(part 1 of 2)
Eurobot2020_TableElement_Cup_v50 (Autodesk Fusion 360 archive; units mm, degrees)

design "TableElement2020" references "Balise Rouge", "Table2020", "Balise Verte"
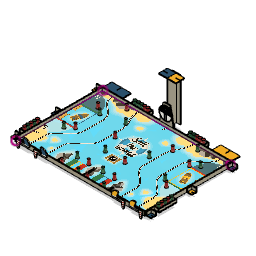
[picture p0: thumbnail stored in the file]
component_insert "Component Insert1"
component_insert "Component Insert21"
component_insert "Component Insert22"
component_insert "Component Insert23"
component_insert "Component Insert24"
component_insert "Component Insert25"
component_insert "Component Insert26"
component_insert "Component Insert27"
component_insert "Component Insert28"
component_insert "Component Insert29"
component_insert "Component Insert30"
component_insert "Component Insert31"
component_insert "Component Insert32"
component_insert "Component Insert33"
component_insert "Component Insert34"
component_insert "Component Insert35"
component_insert "Component Insert36"
component_insert "Component Insert37"
component_insert "Component Insert38"
component_insert "Component Insert39"
component_insert "Component Insert40"
component_insert "Component Insert41"
component_insert "Component Insert42"
component_insert "Component Insert43"
component_insert "Component Insert44"
component_insert "Component Insert45"
component_insert "Component Insert46"
component_insert "Component Insert47"
component_insert "Component Insert48"
component_insert "Component Insert49"
component_insert "Component Insert50"
component_insert "Component Insert51"
component_insert "Component Insert52"
component_insert "Component Insert53"
component_insert "Component Insert54"
component_insert "Component Insert55"
component_insert "Component Insert56"
position "Position1"
joint "Assemble1" OffsetX 0 OffsetY 0 OffsetZ 0 AngleZ 0 OffsetX 0 OffsetY 0 OffsetZ 0 AngleZ 0 alignAngle 0 alignOffsetX 300 alignOffsetY -400 alignOffsetZ 0 OffsetX 0 OffsetY 0 OffsetZ 0 AngleZ 0 OffsetX 0 OffsetY 0 OffsetZ 0 AngleZ 0 OffsetX 0 OffsetY 0 OffsetZ 0 AngleZ 0 OffsetX 0 OffsetY 0 OffsetZ 0 AngleZ 0 OffsetX 0 OffsetY 0 OffsetZ 0 AngleZ 0 OffsetX 0 OffsetY 0 OffsetZ 0 AngleZ 0 OffsetX 0 OffsetY 0 OffsetZ 0 AngleZ 0 OffsetX 0 OffsetY 0 OffsetZ 0 AngleZ 0 OffsetX 0 OffsetY 0 OffsetZ 0 AngleZ 0 OffsetX 0 OffsetY 0 OffsetZ 0 AngleZ 0
joint "Assemble2" OffsetX 0 OffsetY 0 OffsetZ 0 AngleZ 0 OffsetX 0 OffsetY 0 OffsetZ 0 AngleZ 0 alignAngle 0 alignOffsetX 450 alignOffsetY -509 alignOffsetZ 0 OffsetX 0 OffsetY 0 OffsetZ 0 AngleZ 0 OffsetX 0 OffsetY 0 OffsetZ 0 AngleZ 0 OffsetX 0 OffsetY 0 OffsetZ 0 AngleZ 0 OffsetX 0 OffsetY 0 OffsetZ 0 AngleZ 0
joint "Assemble3" OffsetX 0 OffsetY 0 OffsetZ 0 AngleZ 0 OffsetX 0 OffsetY 0 OffsetZ 0 AngleZ 0 alignAngle 0 alignOffsetX 450 alignOffsetY -1080 alignOffsetZ 0 OffsetX 0 OffsetY 0 OffsetZ 0 AngleZ 0 OffsetX 0 OffsetY 0 OffsetZ 0 AngleZ 0
joint "Assemble4" OffsetX 0 OffsetY 0 OffsetZ 0 AngleZ 0 OffsetX 0 OffsetY 0 OffsetZ 0 AngleZ 0 alignAngle 0 alignOffsetX 300 alignOffsetY -1200 alignOffsetZ 0 OffsetX 0 OffsetY 0 OffsetZ 0 AngleZ 0 OffsetX 0 OffsetY 0 OffsetZ 0 AngleZ 0
joint "Assemble5" OffsetX 0 OffsetY 0 OffsetZ 0 AngleZ 0 OffsetX 0 OffsetY 0 OffsetZ 0 AngleZ 0 alignAngle 0 alignOffsetX 670 alignOffsetY -100 alignOffsetZ 0 OffsetX 0 OffsetY 0 OffsetZ 0 AngleZ 0 OffsetX 0 OffsetY 0 OffsetZ 0 AngleZ 0 OffsetX 0 OffsetY 0 OffsetZ 0 AngleZ 0 OffsetX 0 OffsetY 0 OffsetZ 0 AngleZ 0 OffsetX 0 OffsetY 0 OffsetZ 0 AngleZ 0 OffsetX 0 OffsetY 0 OffsetZ 0 AngleZ 0
joint "Assemble6" OffsetX 0 OffsetY 0 OffsetZ 0 AngleZ 0 OffsetX 0 OffsetY 0 OffsetZ 0 AngleZ 0 alignAngle 0 alignOffsetX 950 alignOffsetY -400 alignOffsetZ 0 OffsetX 0 OffsetY 0 OffsetZ 0 AngleZ 0 OffsetX 0 OffsetY 0 OffsetZ 0 AngleZ 0 OffsetX 0 OffsetY 0 OffsetZ 0 AngleZ 0 OffsetX 0 OffsetY 0 OffsetZ 0 AngleZ 0
joint "Assemble7" OffsetX 0 OffsetY 0 OffsetZ 0 AngleZ 0 OffsetX 0 OffsetY 0 OffsetZ 0 AngleZ 0 alignAngle 0 alignOffsetX 1100 alignOffsetY -800 alignOffsetZ 0 OffsetX 0 OffsetY 0 OffsetZ 0 AngleZ 0 OffsetX 0 OffsetY 0 OffsetZ 0 AngleZ 0 OffsetX 0 OffsetY 0 OffsetZ 0 AngleZ 0 OffsetX 0 OffsetY 0 OffsetZ 0 AngleZ 0
joint "Assemble8" OffsetX 0 OffsetY 0 OffsetZ 0 AngleZ 0 OffsetX 0 OffsetY 0 OffsetZ 0 AngleZ 0 alignAngle 0 alignOffsetX 1270 alignOffsetY -1200 alignOffsetZ 0 OffsetX 0 OffsetY 0 OffsetZ 0 AngleZ 0 OffsetX 0 OffsetY 0 OffsetZ 0 AngleZ 0 OffsetX 0 OffsetY 0 OffsetZ 0 AngleZ 0 OffsetX 0 OffsetY 0 OffsetZ 0 AngleZ 0
joint "Assemble9" OffsetX 0 OffsetY 0 OffsetZ 0 AngleZ 0 OffsetX 0 OffsetY 0 OffsetZ 0 AngleZ 0 alignAngle 0 alignOffsetX 1730 alignOffsetY -1200 alignOffsetZ 0 OffsetX 0 OffsetY 0 OffsetZ 0 AngleZ 0 OffsetX 0 OffsetY 0 OffsetZ 0 AngleZ 0
joint "Assemble10" OffsetX 0 OffsetY 0 OffsetZ 0 AngleZ 0 OffsetX 0 OffsetY 0 OffsetZ 0 AngleZ 0 alignAngle 0 alignOffsetX 1900 alignOffsetY -800 alignOffsetZ 0 OffsetX 0 OffsetY 0 OffsetZ 0 AngleZ 0 OffsetX 0 OffsetY 0 OffsetZ 0 AngleZ 0
joint "Assemble11" OffsetX 0 OffsetY 0 OffsetZ 0 AngleZ 0 OffsetX 0 OffsetY 0 OffsetZ 0 AngleZ 0 alignAngle 0 alignOffsetX 2050 alignOffsetY -400 alignOffsetZ 0 OffsetX 0 OffsetY 0 OffsetZ 0 AngleZ 0 OffsetX 0 OffsetY 0 OffsetZ 0 AngleZ 0 OffsetX 0 OffsetY 0 OffsetZ 0 AngleZ 0 OffsetX 0 OffsetY 0 OffsetZ 0 AngleZ 0
joint "Assemble12" OffsetX 0 OffsetY 0 OffsetZ 0 AngleZ 0 OffsetX 0 OffsetY 0 OffsetZ 0 AngleZ 0 alignAngle 0 alignOffsetX 2330 alignOffsetY -100 alignOffsetZ 0 OffsetX 0 OffsetY 0 OffsetZ 0 AngleZ 0 OffsetX 0 OffsetY 0 OffsetZ 0 AngleZ 0
joint "Assemble13" OffsetX 0 OffsetY 0 OffsetZ 0 AngleZ 0 OffsetX 0 OffsetY 0 OffsetZ 0 AngleZ 0 alignAngle 0 alignOffsetX 2700 alignOffsetY -400 alignOffsetZ 0
joint "Assemble14" OffsetX 0 OffsetY 0 OffsetZ 0 AngleZ 0 OffsetX 0 OffsetY 0 OffsetZ 0 AngleZ 0 alignAngle 0 alignOffsetX 2550 alignOffsetY -510 alignOffsetZ 0 OffsetX 0 OffsetY 0 OffsetZ 0 AngleZ 0 OffsetX 0 OffsetY 0 OffsetZ 0 AngleZ 0 OffsetX 0 OffsetY 0 OffsetZ 0 AngleZ 0 OffsetX 0 OffsetY 0 OffsetZ 0 AngleZ 0
joint "Assemble15" OffsetX 0 OffsetY 0 OffsetZ 0 AngleZ 0 OffsetX 0 OffsetY 0 OffsetZ 0 AngleZ 0 alignAngle 0 alignOffsetX 2550 alignOffsetY -1080 alignOffsetZ 0 OffsetX 0 OffsetY 0 OffsetZ 0 AngleZ 0 OffsetX 0 OffsetY 0 OffsetZ 0 AngleZ 0 OffsetX 0 OffsetY 0 OffsetZ 0 AngleZ 0 OffsetX 0 OffsetY 0 OffsetZ 0 AngleZ 0
joint "Assemble16" OffsetX 0 OffsetY 0 OffsetZ 0 AngleZ 0 OffsetX 0 OffsetY 0 OffsetZ 0 AngleZ 0 alignAngle 0 alignOffsetX 2700 alignOffsetY -1200 alignOffsetZ 0
joint "Assemble17" OffsetX 0 OffsetY 0 OffsetZ 0 AngleZ 0 OffsetX 0 OffsetY 0 OffsetZ 0 AngleZ 0 alignAngle 0 alignOffsetX 1335 alignOffsetY -1650 alignOffsetZ 0 OffsetX 0 OffsetY 0 OffsetZ 0 AngleZ 0 OffsetX 0 OffsetY 0 OffsetZ 0 AngleZ 0 OffsetX 0 OffsetY 0 OffsetZ 0 AngleZ 0 OffsetX 0 OffsetY 0 OffsetZ 0 AngleZ 0
joint "Assemble18" OffsetX 0 OffsetY 0 OffsetZ 0 AngleZ 0 OffsetX 0 OffsetY 0 OffsetZ 0 AngleZ 0 alignAngle 0 alignOffsetX 1065 alignOffsetY -1650 alignOffsetZ 0 OffsetX 0 OffsetY 0 OffsetZ 0 AngleZ 0 OffsetX 0 OffsetY 0 OffsetZ 0 AngleZ 0 OffsetX 0 OffsetY 0 OffsetZ 0 AngleZ 0 OffsetX 0 OffsetY 0 OffsetZ 0 AngleZ 0
joint "Assemble19" OffsetX 0 OffsetY 0 OffsetZ 0 AngleZ 0 OffsetX 0 OffsetY 0 OffsetZ 0 AngleZ 0 alignAngle 0 alignOffsetX 1005 alignOffsetY -1955 alignOffsetZ 0 OffsetX 0 OffsetY 0 OffsetZ 0 AngleZ 0 OffsetX 0 OffsetY 0 OffsetZ 0 AngleZ 0 OffsetX 0 OffsetY 0 OffsetZ 0 AngleZ 0 OffsetX 0 OffsetY 0 OffsetZ 0 AngleZ 0 OffsetX 0 OffsetY 0 OffsetZ 0 AngleZ 0 OffsetX 0 OffsetY 0 OffsetZ 0 AngleZ 0 OffsetX 0 OffsetY 0 OffsetZ 0 AngleZ 0 OffsetX 0 OffsetY 0 OffsetZ 0 AngleZ 0
joint "Assemble20" OffsetX 0 OffsetY 0 OffsetZ 0 AngleZ 0 OffsetX 0 OffsetY 0 OffsetZ 0 AngleZ 0 alignAngle 0 alignOffsetX 1395 alignOffsetY -1955 alignOffsetZ 0 OffsetX 0 OffsetY 0 OffsetZ 0 AngleZ 0 OffsetX 0 OffsetY 0 OffsetZ 0 AngleZ 0 OffsetX 0 OffsetY 0 OffsetZ 0 AngleZ 0 OffsetX 0 OffsetY 0 OffsetZ 0 AngleZ 0
joint "Assemble21" OffsetX 0 OffsetY 0 OffsetZ 0 AngleZ 0 OffsetX 0 OffsetY 0 OffsetZ 0 AngleZ 0 alignAngle 0 alignOffsetX 1935 alignOffsetY -1650 alignOffsetZ 0 OffsetX 0 OffsetY 0 OffsetZ 0 AngleZ 0 OffsetX 0 OffsetY 0 OffsetZ 0 AngleZ 0 OffsetX 0 OffsetY 0 OffsetZ 0 AngleZ 0 OffsetX 0 OffsetY 0 OffsetZ 0 AngleZ 0
joint "Assemble22" OffsetX 0 OffsetY 0 OffsetZ 0 AngleZ 0 OffsetX 0 OffsetY 0 OffsetZ 0 AngleZ 0 alignAngle 0 alignOffsetX 1665 alignOffsetY -1650 alignOffsetZ 0 OffsetX 0 OffsetY 0 OffsetZ 0 AngleZ 0 OffsetX 0 OffsetY 0 OffsetZ 0 AngleZ 0 OffsetX 0 OffsetY 0 OffsetZ 0 AngleZ 0 OffsetX 0 OffsetY 0 OffsetZ 0 AngleZ 0
joint "Assemble23" OffsetX 0 OffsetY 0 OffsetZ 0 AngleZ 0 OffsetX 0 OffsetY 0 OffsetZ 0 AngleZ 0 alignAngle 0 alignOffsetX 1605 alignOffsetY -1955 alignOffsetZ 0 OffsetX 0 OffsetY 0 OffsetZ 0 AngleZ 0 OffsetX 0 OffsetY 0 OffsetZ 0 AngleZ 0 OffsetX 0 OffsetY 0 OffsetZ 0 AngleZ 0 OffsetX 0 OffsetY 0 OffsetZ 0 AngleZ 0
joint "Assemble24" OffsetX 0 OffsetY 0 OffsetZ 0 AngleZ 0 OffsetX 0 OffsetY 0 OffsetZ 0 AngleZ 0 alignAngle 0 alignOffsetX 1995 alignOffsetY -1955 alignOffsetZ 0 OffsetX 0 OffsetY 0 OffsetZ 0 AngleZ 0 OffsetX 0 OffsetY 0 OffsetZ 0 AngleZ 0 OffsetX 0 OffsetY 0 OffsetZ 0 AngleZ 0 OffsetX 0 OffsetY 0 OffsetZ 0 AngleZ 0
joint "Assemble25" OffsetX 0 OffsetY 0 OffsetZ 0 AngleZ 0 OffsetX 0 OffsetY 0 OffsetZ 0 AngleZ 0 alignAngle 0 alignOffsetX -67 (= "-22 mm - 45 mm") alignOffsetY -1450 alignOffsetZ 130 OffsetX 0 OffsetY 0 OffsetZ 0 AngleZ 0 OffsetX 0 OffsetY 0 OffsetZ 0 AngleZ 0 OffsetX 0 OffsetY 0 OffsetZ 0 AngleZ 0 OffsetX 0 OffsetY 0 OffsetZ 0 AngleZ 0 OffsetX 0 OffsetY 0 OffsetZ 0 AngleZ 0 OffsetX 0 OffsetY 0 OffsetZ 0 AngleZ 0 OffsetX 0 OffsetY 0 OffsetZ 0 AngleZ 0 OffsetX 0 OffsetY 0 OffsetZ 0 AngleZ 0 OffsetX 0 OffsetY 0 OffsetZ 0 AngleZ 0 OffsetX 0 OffsetY 0 OffsetZ 0 AngleZ 0 OffsetX 0 OffsetY 0 OffsetZ 0 AngleZ 0 OffsetX 0 OffsetY 0 OffsetZ 0 AngleZ 0 OffsetX 0 OffsetY 0 OffsetZ 0 AngleZ 0 OffsetX 0 OffsetY 0 OffsetZ 0 AngleZ 0 OffsetX 0 OffsetY 0 OffsetZ 0 AngleZ 0 OffsetX 0 OffsetY 0 OffsetZ 0 AngleZ 0
joint "Assemble26" OffsetX 0 OffsetY 0 OffsetZ 0 AngleZ 0 OffsetX 0 OffsetY 0 OffsetZ 0 AngleZ 0 alignAngle 0 alignOffsetX -67 (= "-22 mm - 45 mm") alignOffsetY -1525 alignOffsetZ 130 OffsetX 0 OffsetY 0 OffsetZ 0 AngleZ 0 OffsetX 0 OffsetY 0 OffsetZ 0 AngleZ 0 OffsetX 0 OffsetY 0 OffsetZ 0 AngleZ 0 OffsetX 0 OffsetY 0 OffsetZ 0 AngleZ 0 OffsetX 0 OffsetY 0 OffsetZ 0 AngleZ 0 OffsetX 0 OffsetY 0 OffsetZ 0 AngleZ 0 OffsetX 0 OffsetY 0 OffsetZ 0 AngleZ 0 OffsetX 0 OffsetY 0 OffsetZ 0 AngleZ 0 OffsetX 0 OffsetY 0 OffsetZ 0 AngleZ 0 OffsetX 0 OffsetY 0 OffsetZ 0 AngleZ 0 OffsetX 0 OffsetY 0 OffsetZ 0 AngleZ 0 OffsetX 0 OffsetY 0 OffsetZ 0 AngleZ 0
joint "Assemble27" OffsetX 0 OffsetY 0 OffsetZ 0 AngleZ 0 OffsetX 0 OffsetY 0 OffsetZ 0 AngleZ 0 alignAngle 0 alignOffsetX -67 (= "-22 mm - 45 mm") alignOffsetY -1600 alignOffsetZ 130 OffsetX 0 OffsetY 0 OffsetZ 0 AngleZ 0 OffsetX 0 OffsetY 0 OffsetZ 0 AngleZ 0 OffsetX 0 OffsetY 0 OffsetZ 0 AngleZ 0 OffsetX 0 OffsetY 0 OffsetZ 0 AngleZ 0 OffsetX 0 OffsetY 0 OffsetZ 0 AngleZ 0 OffsetX 0 OffsetY 0 OffsetZ 0 AngleZ 0 OffsetX 0 OffsetY 0 OffsetZ 0 AngleZ 0 OffsetX 0 OffsetY 0 OffsetZ 0 AngleZ 0 OffsetX 0 OffsetY 0 OffsetZ 0 AngleZ 0 OffsetX 0 OffsetY 0 OffsetZ 0 AngleZ 0 OffsetX 0 OffsetY 0 OffsetZ 0 AngleZ 0 OffsetX 0 OffsetY 0 OffsetZ 0 AngleZ 0 OffsetX 0 OffsetY 0 OffsetZ 0 AngleZ 0 OffsetX 0 OffsetY 0 OffsetZ 0 AngleZ 0
component_insert "Component Insert66"
joint "Assemble40" OffsetX 0 OffsetY 0 OffsetZ 0 AngleZ 0 OffsetX 0 OffsetY 0 OffsetZ 0 AngleZ 0 alignAngle 0 alignOffsetX -67 alignOffsetY -1675 alignOffsetZ 130 OffsetX 0 OffsetY 0 OffsetZ 0 AngleZ 0 OffsetX 0 OffsetY 0 OffsetZ 0 AngleZ 0 OffsetX 0 OffsetY 0 OffsetZ 0 AngleZ 0 OffsetX 0 OffsetY 0 OffsetZ 0 AngleZ 0 OffsetX 0 OffsetY 0 OffsetZ 0 AngleZ 0 OffsetX 0 OffsetY 0 OffsetZ 0 AngleZ 0 OffsetX 0 OffsetY 0 OffsetZ 0 AngleZ 0 OffsetX 0 OffsetY 0 OffsetZ 0 AngleZ 0
component_insert "Component Insert73"
joint "Assemble46" OffsetX 0 OffsetY 0 OffsetZ 0 AngleZ 0 OffsetX 0 OffsetY 0 OffsetZ 0 AngleZ 0 alignAngle 0 alignOffsetX -67 alignOffsetY -1750 alignOffsetZ 15 OffsetX 0 OffsetY 0 OffsetZ 0 AngleZ 0 OffsetX 0 OffsetY 0 OffsetZ 0 AngleZ 0
joint "Assemble28" OffsetX 0 OffsetY 0 OffsetZ 0 AngleZ 0 OffsetX 0 OffsetY 0 OffsetZ 0 AngleZ 0 alignAngle 0 alignOffsetX 3067 alignOffsetY -1675 alignOffsetZ 130 OffsetX 0 OffsetY 0 OffsetZ 0 AngleZ 0 OffsetX 0 OffsetY 0 OffsetZ 0 AngleZ 0 OffsetX 0 OffsetY 0 OffsetZ 0 AngleZ 0 OffsetX 0 OffsetY 0 OffsetZ 0 AngleZ 0 OffsetX 0 OffsetY 0 OffsetZ 0 AngleZ 0 OffsetX 0 OffsetY 0 OffsetZ 0 AngleZ 0 OffsetX 0 OffsetY 0 OffsetZ 0 AngleZ 0 OffsetX 0 OffsetY 0 OffsetZ 0 AngleZ 0 OffsetX 0 OffsetY 0 OffsetZ 0 AngleZ 0 OffsetX 0 OffsetY 0 OffsetZ 0 AngleZ 0 OffsetX 0 OffsetY 0 OffsetZ 0 AngleZ 0 OffsetX 0 OffsetY 0 OffsetZ 0 AngleZ 0 OffsetX 0 OffsetY 0 OffsetZ 0 AngleZ 0 OffsetX 0 OffsetY 0 OffsetZ 0 AngleZ 0
joint "Assemble29" OffsetX 0 OffsetY 0 OffsetZ 0 AngleZ 0 OffsetX 0 OffsetY 0 OffsetZ 0 AngleZ 0 alignAngle 0 alignOffsetX 3067 alignOffsetY -1750 alignOffsetZ 130 OffsetX 0 OffsetY 0 OffsetZ 0 AngleZ 0 OffsetX 0 OffsetY 0 OffsetZ 0 AngleZ 0 OffsetX 0 OffsetY 0 OffsetZ 0 AngleZ 0 OffsetX 0 OffsetY 0 OffsetZ 0 AngleZ 0 OffsetX 0 OffsetY 0 OffsetZ 0 AngleZ 0 OffsetX 0 OffsetY 0 OffsetZ 0 AngleZ 0 OffsetX 0 OffsetY 0 OffsetZ 0 AngleZ 0 OffsetX 0 OffsetY 0 OffsetZ 0 AngleZ 0 OffsetX 0 OffsetY 0 OffsetZ 0 AngleZ 0 OffsetX 0 OffsetY 0 OffsetZ 0 AngleZ 0 OffsetX 0 OffsetY 0 OffsetZ 0 AngleZ 0 OffsetX 0 OffsetY 0 OffsetZ 0 AngleZ 0 OffsetX 0 OffsetY 0 OffsetZ 0 AngleZ 0 OffsetX 0 OffsetY 0 OffsetZ 0 AngleZ 0
joint "Assemble30" OffsetX 0 OffsetY 0 OffsetZ 0 AngleZ 0 OffsetX 0 OffsetY 0 OffsetZ 0 AngleZ 0 alignAngle 0 alignOffsetX 3067 alignOffsetY -1525 alignOffsetZ 130 OffsetX 0 OffsetY 0 OffsetZ 0 AngleZ 0 OffsetX 0 OffsetY 0 OffsetZ 0 AngleZ 0 OffsetX 0 OffsetY 0 OffsetZ 0 AngleZ 0 OffsetX 0 OffsetY 0 OffsetZ 0 AngleZ 0 OffsetX 0 OffsetY 0 OffsetZ 0 AngleZ 0 OffsetX 0 OffsetY 0 OffsetZ 0 AngleZ 0 OffsetX 0 OffsetY 0 OffsetZ 0 AngleZ 0 OffsetX 0 OffsetY 0 OffsetZ 0 AngleZ 0 OffsetX 0 OffsetY 0 OffsetZ 0 AngleZ 0 OffsetX 0 OffsetY 0 OffsetZ 0 AngleZ 0 OffsetX 0 OffsetY 0 OffsetZ 0 AngleZ 0 OffsetX 0 OffsetY 0 OffsetZ 0 AngleZ 0 OffsetX 0 OffsetY 0 OffsetZ 0 AngleZ 0 OffsetX 0 OffsetY 0 OffsetZ 0 AngleZ 0 OffsetX 0 OffsetY 0 OffsetZ 0 AngleZ 0 OffsetX 0 OffsetY 0 OffsetZ 0 AngleZ 0
component_insert "Component Insert67"
joint "Assemble41" OffsetX 0 OffsetY 0 OffsetZ 0 AngleZ 0 OffsetX 0 OffsetY 0 OffsetZ 0 AngleZ 0 alignAngle 0 alignOffsetX 3067 alignOffsetY -1600 alignOffsetZ 130 OffsetX 0 OffsetY 0 OffsetZ 0 AngleZ 0 OffsetX 0 OffsetY 0 OffsetZ 0 AngleZ 0 OffsetX 0 OffsetY 0 OffsetZ 0 AngleZ 0 OffsetX 0 OffsetY 0 OffsetZ 0 AngleZ 0 OffsetX 0 OffsetY 0 OffsetZ 0 AngleZ 0 OffsetX 0 OffsetY 0 OffsetZ 0 AngleZ 0 OffsetX 0 OffsetY 0 OffsetZ 0 AngleZ 0 OffsetX 0 OffsetY 0 OffsetZ 0 AngleZ 0
component_insert "Component Insert74"
joint "Assemble47" OffsetX 0 OffsetY 0 OffsetZ 0 AngleZ 0 OffsetX 0 OffsetY 0 OffsetZ 0 AngleZ 0 alignAngle 180 alignOffsetX 3067 alignOffsetY -1450 alignOffsetZ 15 OffsetX 0 OffsetY 0 OffsetZ 0 AngleZ 0 OffsetX 0 OffsetY 0 OffsetZ 0 AngleZ 0 OffsetX 0 OffsetY 0 OffsetZ 0 AngleZ 0 OffsetX 0 OffsetY 0 OffsetZ 0 AngleZ 0
ground "Ground1"
ground "Ground2"
joint "Assemble31" OffsetX 0 OffsetY 0 OffsetZ 0 AngleZ 0 OffsetX 0 OffsetY 0 OffsetZ 0 AngleZ 0 alignAngle 0 alignOffsetX 700 alignOffsetY 67 (= "22 mm + 45 mm") alignOffsetZ 130 OffsetX 0 OffsetY 0 OffsetZ 0 AngleZ 0 OffsetX 0 OffsetY 0 OffsetZ 0 AngleZ 0 OffsetX 0 OffsetY 0 OffsetZ 0 AngleZ 0 OffsetX 0 OffsetY 0 OffsetZ 0 AngleZ 0 OffsetX 0 OffsetY 0 OffsetZ 0 AngleZ 0 OffsetX 0 OffsetY 0 OffsetZ 0 AngleZ 0 OffsetX 0 OffsetY 0 OffsetZ 0 AngleZ 0 OffsetX 0 OffsetY 0 OffsetZ 0 AngleZ 0 OffsetX 0 OffsetY 0 OffsetZ 0 AngleZ 0 OffsetX 0 OffsetY 0 OffsetZ 0 AngleZ 0
joint "Assemble32" OffsetX 0 OffsetY 0 OffsetZ 0 AngleZ 0 OffsetX 0 OffsetY 0 OffsetZ 0 AngleZ 0 alignAngle 0 alignOffsetX 850 alignOffsetY 67 alignOffsetZ 130 OffsetX 0 OffsetY 0 OffsetZ 0 AngleZ 0 OffsetX 0 OffsetY 0 OffsetZ 0 AngleZ 0 OffsetX 0 OffsetY 0 OffsetZ 0 AngleZ 0 OffsetX 0 OffsetY 0 OffsetZ 0 AngleZ 0 OffsetX 0 OffsetY 0 OffsetZ 0 AngleZ 0 OffsetX 0 OffsetY 0 OffsetZ 0 AngleZ 0 OffsetX 0 OffsetY 0 OffsetZ 0 AngleZ 0 OffsetX 0 OffsetY 0 OffsetZ 0 AngleZ 0 OffsetX 0 OffsetY 0 OffsetZ 0 AngleZ 0 OffsetX 0 OffsetY 0 OffsetZ 0 AngleZ 0
joint "Assemble33" OffsetX 0 OffsetY 0 OffsetZ 0 AngleZ 0 OffsetX 0 OffsetY 0 OffsetZ 0 AngleZ 0 alignAngle 0 alignOffsetX 1000 alignOffsetY 67 alignOffsetZ 130 OffsetX 0 OffsetY 0 OffsetZ 0 AngleZ 0 OffsetX 0 OffsetY 0 OffsetZ 0 AngleZ 0 OffsetX 0 OffsetY 0 OffsetZ 0 AngleZ 0 OffsetX 0 OffsetY 0 OffsetZ 0 AngleZ 0 OffsetX 0 OffsetY 0 OffsetZ 0 AngleZ 0 OffsetX 0 OffsetY 0 OffsetZ 0 AngleZ 0 OffsetX 0 OffsetY 0 OffsetZ 0 AngleZ 0 OffsetX 0 OffsetY 0 OffsetZ 0 AngleZ 0 OffsetX 0 OffsetY 0 OffsetZ 0 AngleZ 0 OffsetX 0 OffsetY 0 OffsetZ 0 AngleZ 0
component_insert "Component Insert63"
joint "Assemble37" OffsetX 0 OffsetY 0 OffsetZ 0 AngleZ 0 OffsetX 0 OffsetY 0 OffsetZ 0 AngleZ 0 alignAngle 0 alignOffsetX 925 alignOffsetY 67 alignOffsetZ 130 OffsetX 0 OffsetY 0 OffsetZ 0 AngleZ 0 OffsetX 0 OffsetY 0 OffsetZ 0 AngleZ 0 OffsetX 0 OffsetY 0 OffsetZ 0 AngleZ 0 OffsetX 0 OffsetY 0 OffsetZ 0 AngleZ 0 OffsetX 0 OffsetY 0 OffsetZ 0 AngleZ 0 OffsetX 0 OffsetY 0 OffsetZ 0 AngleZ 0
component_insert "Component Insert70"
joint "Assemble44" OffsetX 0 OffsetY 0 OffsetZ 0 AngleZ 0 OffsetX 0 OffsetY 0 OffsetZ 0 AngleZ 0 alignAngle 180 alignOffsetX 775 alignOffsetY 67 alignOffsetZ 15 OffsetX 0 OffsetY 0 OffsetZ 0 AngleZ 0 OffsetX 0 OffsetY 0 OffsetZ 0 AngleZ 0 OffsetX 0 OffsetY 0 OffsetZ 0 AngleZ 0 OffsetX 0 OffsetY 0 OffsetZ 0 AngleZ 0
joint "Assemble34" OffsetX 0 OffsetY 0 OffsetZ 0 AngleZ 0 OffsetX 0 OffsetY 0 OffsetZ 0 AngleZ 0 alignAngle 0 alignOffsetX 2000 alignOffsetY 67 alignOffsetZ 130 OffsetX 0 OffsetY 0 OffsetZ 0 AngleZ 0 OffsetX 0 OffsetY 0 OffsetZ 0 AngleZ 0 OffsetX 0 OffsetY 0 OffsetZ 0 AngleZ 0 OffsetX 0 OffsetY 0 OffsetZ 0 AngleZ 0 OffsetX 0 OffsetY 0 OffsetZ 0 AngleZ 0 OffsetX 0 OffsetY 0 OffsetZ 0 AngleZ 0 OffsetX 0 OffsetY 0 OffsetZ 0 AngleZ 0 OffsetX 0 OffsetY 0 OffsetZ 0 AngleZ 0 OffsetX 0 OffsetY 0 OffsetZ 0 AngleZ 0 OffsetX 0 OffsetY 0 OffsetZ 0 AngleZ 0
joint "Assemble35" OffsetX 0 OffsetY 0 OffsetZ 0 AngleZ 0 OffsetX 0 OffsetY 0 OffsetZ 0 AngleZ 0 alignAngle 0 alignOffsetX 2150 alignOffsetY 67 alignOffsetZ 130 OffsetX 0 OffsetY 0 OffsetZ 0 AngleZ 0 OffsetX 0 OffsetY 0 OffsetZ 0 AngleZ 0 OffsetX 0 OffsetY 0 OffsetZ 0 AngleZ 0 OffsetX 0 OffsetY 0 OffsetZ 0 AngleZ 0 OffsetX 0 OffsetY 0 OffsetZ 0 AngleZ 0 OffsetX 0 OffsetY 0 OffsetZ 0 AngleZ 0 OffsetX 0 OffsetY 0 OffsetZ 0 AngleZ 0 OffsetX 0 OffsetY 0 OffsetZ 0 AngleZ 0 OffsetX 0 OffsetY 0 OffsetZ 0 AngleZ 0 OffsetX 0 OffsetY 0 OffsetZ 0 AngleZ 0 OffsetX 0 OffsetY 0 OffsetZ 0 AngleZ 0 OffsetX 0 OffsetY 0 OffsetZ 0 AngleZ 0 OffsetX 0 OffsetY 0 OffsetZ 0 AngleZ 0 OffsetX 0 OffsetY 0 OffsetZ 0 AngleZ 0 OffsetX 0 OffsetY 0 OffsetZ 0 AngleZ 0 OffsetX 0 OffsetY 0 OffsetZ 0 AngleZ 0 OffsetX 0 OffsetY 0 OffsetZ 0 AngleZ 0 OffsetX 0 OffsetY 0 OffsetZ 0 AngleZ 0 OffsetX 0 OffsetY 0 OffsetZ 0 AngleZ 0 OffsetX 0 OffsetY 0 OffsetZ 0 AngleZ 0
joint "Assemble36" OffsetX 0 OffsetY 0 OffsetZ 0 AngleZ 0 OffsetX 0 OffsetY 0 OffsetZ 0 AngleZ 0 alignAngle 0 alignOffsetX 2075 alignOffsetY 67 alignOffsetZ 130 OffsetX 0 OffsetY 0 OffsetZ 0 AngleZ 0 OffsetX 0 OffsetY 0 OffsetZ 0 AngleZ 0 OffsetX 0 OffsetY 0 OffsetZ 0 AngleZ 0 OffsetX 0 OffsetY 0 OffsetZ 0 AngleZ 0 OffsetX 0 OffsetY 0 OffsetZ 0 AngleZ 0 OffsetX 0 OffsetY 0 OffsetZ 0 AngleZ 0 OffsetX 0 OffsetY 0 OffsetZ 0 AngleZ 0 OffsetX 0 OffsetY 0 OffsetZ 0 AngleZ 0 OffsetX 0 OffsetY 0 OffsetZ 0 AngleZ 0 OffsetX 0 OffsetY 0 OffsetZ 0 AngleZ 0 OffsetX 0 OffsetY 0 OffsetZ 0 AngleZ 0 OffsetX 0 OffsetY 0 OffsetZ 0 AngleZ 0 OffsetX 0 OffsetY 0 OffsetZ 0 AngleZ 0 OffsetX 0 OffsetY 0 OffsetZ 0 AngleZ 0
component_insert "Component Insert64"
joint "Assemble38" OffsetX 0 OffsetY 0 OffsetZ 0 AngleZ 0 OffsetX 0 OffsetY 0 OffsetZ 0 AngleZ 0 alignAngle 0 alignOffsetX 2225 alignOffsetY 67 alignOffsetZ 130 OffsetX 0 OffsetY 0 OffsetZ 0 AngleZ 0 OffsetX 0 OffsetY 0 OffsetZ 0 AngleZ 0 OffsetX 0 OffsetY 0 OffsetZ 0 AngleZ 0 OffsetX 0 OffsetY 0 OffsetZ 0 AngleZ 0 OffsetX 0 OffsetY 0 OffsetZ 0 AngleZ 0 OffsetX 0 OffsetY 0 OffsetZ 0 AngleZ 0 OffsetX 0 OffsetY 0 OffsetZ 0 AngleZ 0 OffsetX 0 OffsetY 0 OffsetZ 0 AngleZ 0
component_insert "Component Insert72"
joint "Assemble45" OffsetX 0 OffsetY 0 OffsetZ 0 AngleZ 0 OffsetX 0 OffsetY 0 OffsetZ 0 AngleZ 0 alignAngle 180 alignOffsetX 2300 alignOffsetY 67 alignOffsetZ 15 OffsetX 0 OffsetY 0 OffsetZ 0 AngleZ 0 OffsetX 0 OffsetY 0 OffsetZ 0 AngleZ 0

design "manchonJaune"
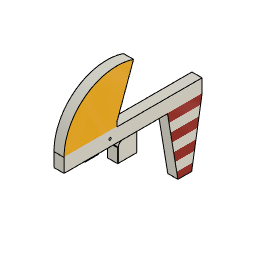
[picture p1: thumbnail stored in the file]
sketch "Sketch1" plane through (0, 0, 0) normal (1, 0, 0) x axis (0, 1, 0)
  line L1 (15, 15) -> (15, 25)
  line L2 (200, 15) -> (15, 15)
  line L3 (-100, -15) -> (125, -15)
  line L4 (-100, 15) -> (-100, -15)
  line L5 (200, 15) -> (200, -15)
  line L6 (177.5, -150) -> (200, -15)
  line L7 (147.5, -150) -> (177.5, -150)
  line L8 (125, -15) -> (147.5, -150)
  line L9 (0, 0) -> (200, 0)
  line L10 (15, 15) -> (-15, 15)
  line L11 (0, 15) -> (0, 0)
  line L12 (51.101, 124.1866) -> (15, 25)
  circle C1 centre (0, 0) radius 2.5
  circle C2 centre (15, 15) radius 115
  point P1 (0, 0)
  point P2 (0, 0)
  point P13 (200, 0)
  point P14 (0, 0)
  point P15 (0, 0)
  point P16 (0, 15)
  point P9 (-100, 15)
  point P5 (15, 15)
  point P17 (15, 15)
  point P18 (51.101, 124.1866)
  point P7 (125, -15)
  point P10 (200, -15)
  point P11 (177.5, -150)
  point P12 (147.5, -150)
  point P8 (-100, -15)
  point P4 (15, 25)
  coincident P1 P2
  perpendicular L1 L2
  horizontal L3
  perpendicular L3 L4
  vertical L5
  equal L4 L5
  parallel L3 L7
  equal L6 L8
  midpoint L5 P13
  coincident P1 P14
  horizontal L9
  coincident P1 P15
  midpoint L10 P16
  vertical L11
  coincident L2 P9
  horizontal L2
  horizontal L10
  equal L4 L10
  coincident P5 P17
  coincident P9 C2
  coincident C2 P18
  dimension "d1" diameter C1 = 5
  dimension "d2" distance P1 L4 = 100
  dimension "d4" distance P2 L5 = 200
  dimension "d8" distance P7 P10 = 75
  dimension "d9" distance P11 P12 = 30
  dimension "d11" distance P8 P9 = 30
  dimension "d12" distance P4 P5 = 10
  dimension "d22" distance L7 L9 = 150
  dimension "d23" angle L2 L12 = 70
  dimension "d36" OffsetX = 0
  dimension "d37" OffsetY = 0
  dimension "d38" OffsetZ = 0
  dimension "d39" AngleZ = 0
  dimension "d48" OffsetX = 0
  dimension "d49" OffsetY = 0
  dimension "d50" OffsetZ = 0
  dimension "d51" AngleZ = 0
extrude "Extrude1" new body sketch "Sketch1" profile of C1 L1 L2 L3 L4 L5 L6 L7 L8 C2 L12 along normal blind 22
sketch "Sketch1" plane through (0, 0, 0) normal (1, 0, 0) x axis (0, 0, -1)
  line L1 (55, 15) -> (15, 15)
  line L2 (55, 55) -> (55, 15)
  line L3 (15, 55) -> (55, 55)
  line L4 (15, 15) -> (15, 55)
  line L5 (15, -100) -> (15, 125)
  line L6 (25, 15) -> (15, 15)
  arc A1 centre (25, 25) radius 10 clockwise from (25, 15) to (15, 25)
  point P8 (25, 15)
  point P9 (15, 25)
  point P1 (0, 0)
  horizontal L1
  vertical L2
  horizontal L3
  vertical L4
  coincident L1 P8
  perpendicular L5 L6
  tangent L6 A1
  coincident L4 P9
  tangent L4 A1
  dimension "d24" distance P1 L1 = 15
  dimension "d25" distance P1 L4 = 15
  dimension "d26" distance P1 L5 = 15
  dimension "d27" distance L4 P8 = 10
  dimension "d28" distance L1 L3 = 40
  dimension "d29" distance L2 L4 = 40
  dimension "d32" OffsetX = 0
  dimension "d33" OffsetY = 0
  dimension "d34" OffsetZ = 0
  dimension "d35" AngleZ = 0
  dimension "d44" OffsetX = 0
  dimension "d45" OffsetY = 0
  dimension "d46" OffsetZ = 0
  dimension "d47" AngleZ = 0
extrude "Extrude1" new body sketch "Sketch1" profile of L1 L2 L3 L4 L5 A1 along normal blind 22
joint "Assemble1" alignAngle 0 alignOffsetX -25 alignOffsetY -28 alignOffsetZ 0
decal "Decal1"
decal "Decal2"
sketch "Sketch1" plane through (0, 18, 0) normal (0, -1, 0) x axis (1, 0, 0)
  line L1 (0, -55) -> (0, -25)
  line L2 (22, -55) -> (0, -55)
  line L3 (22, -25) -> (22, -55)
  line L4 (0, -25) -> (22, -25)
extrude "Extrude1" new body sketch "Sketch1" along normal blind 1.5
position "Position1" RotateAboutZ -90
sketch "Sketch2" plane through (0, 0, -15) normal (0, 0, -1) x axis (1, 0, 0)
  line L1 (0, -125) -> (0, 100)
  line L2 (22, -125) -> (0, -125)
  line L3 (22, 100) -> (22, -125)
  line L4 (0, 100) -> (22, 100)
  line L5 (0, 55) -> (0, 25)
  line L6 (22, 55) -> (0, 55)
  line L7 (22, 25) -> (22, 55)
  line L8 (0, 25) -> (22, 25)
extrude "Extrude2" new body sketch "Sketch2" profile of L1 L3 L5 L6 L7 L8 along normal blind 1.5
position "Position2" RotateAboutZ 0
joint "Assemble2" alignAngle 0 alignOffsetX 0 alignOffsetY 0 alignOffsetZ 0
joint "Assemble3" alignAngle 0 alignOffsetX 0 alignOffsetY 45 alignOffsetZ 0
copy_paste_bodies "CutPasteBodies"
component_from_bodies "Body->Comp"
joint "Assemble4" alignAngle 0 alignOffsetX 0 alignOffsetY 45 alignOffsetZ 0
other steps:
base_feature "Base Feature1"
base_feature "Base Feature1"
create_component "CreateComponent1"
create_component "CreateComponent2"
joint_origin "JointOrigin3" OffsetX 0 OffsetY 0 OffsetZ 0 AngleZ 0
joint_origin "JointOrigin3" OffsetX 0 OffsetY 0 OffsetZ 0 AngleZ 0
joint_origin "JointOrigin1" OffsetX 0 OffsetY 0 OffsetZ 0 AngleZ 0
joint_origin "JointOrigin4" OffsetX 0 OffsetY 0 OffsetZ 0 AngleZ 0
joint_origin "JointOrigin2" OffsetX 0 OffsetY 0 OffsetZ 0 AngleZ 0
joint_origin "JointOrigin4" OffsetX 0 OffsetY 0 OffsetZ 0 AngleZ 0
remove_body "RemoveBody1"
create_component "CreateComponent3"
remove_body "RemoveBody1"
joint_origin "JointOrigin1" OffsetX 0 OffsetY 0 OffsetZ 0 AngleZ 0
joint_origin "JointOrigin5" OffsetX 0 OffsetY 0 OffsetZ 0 AngleZ 0

design "PaintExperience"
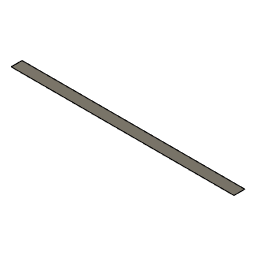
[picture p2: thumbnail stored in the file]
sketch "Sketch1" plane through (0, 0, 0) normal (0, 1, 0) x axis (1, 0, 0)
  line L1 (450, 0) -> (0, 0)
  line L2 (0, 0) -> (450, -22)
  line L3 (0, 0) -> (0, -22)
  line L4 (0, 0) -> (0, 0)
  point P1 (0, 0)
  point P2 (0, 0)
  point P3 (450, 0)
  point P5 (0, -22)
  horizontal L1
  vertical L2
  horizontal L3
  vertical L4
  coincident P1 P2
  dimension "d1" distance P2 P3 = 450
  dimension "d2" distance P2 P5 = 22
extrude "Extrude1" new body sketch "Sketch1" along normal blind 0.1

design "EdgeBeacons_SmallBorder"
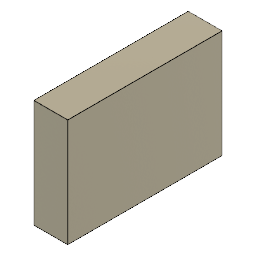
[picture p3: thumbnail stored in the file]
sketch "Sketch1" plane through (0, 0, 0) normal (1, 0, 0) x axis (0, 0, -1)
  line L1 (100, 70) -> (0, 70)
  line L2 (100, 0) -> (100, 70)
  line L3 (0, 0) -> (100, 0)
  line L4 (0, 70) -> (0, 0)
  point P1 (0, 0)
  point P5 (0, 0)
  point P2 (0, 70)
  point P3 (100, 70)
  horizontal L1
  vertical L2
  horizontal L3
  vertical L4
  coincident P1 P5
  dimension "d1" distance P2 P5 = 70 (= "48 mm + 22 mm")
  dimension "d2" distance P2 P3 = 100 (= "122 mm - 22 mm")
extrude "Extrude1" new body sketch "Sketch1" along normal blind 22

design "BaseTable" references "BorderSmall", "MiddleBeaconVertSupport2", "Edge Beacon Right", "Ground", "Edge Beacon Left", "MiddleBeaconVertSupport1", "BorderLong", "MiddleBeaconTop"
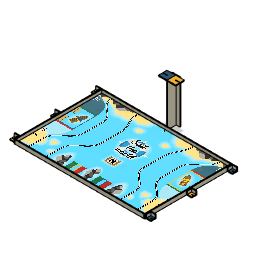
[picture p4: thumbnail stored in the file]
component_insert "Component Insert1"
ground "Ground4"
component_insert "Component Insert2"
component_insert "Component Insert3"
component_insert "Component Insert4"
component_insert "Component Insert5"
joint "Assemble1" OffsetX 0 OffsetY 0 OffsetZ 0 AngleZ 0 OffsetX 0 OffsetY 0 OffsetZ 0 AngleZ 0 alignAngle 0 alignOffsetX 0 alignOffsetY 0 alignOffsetZ 0
joint "Assemble2" OffsetX 0 OffsetY 0 OffsetZ 0 AngleZ 0 OffsetX 0 OffsetY 0 OffsetZ 0 AngleZ 0 alignAngle 0 alignOffsetX 0 alignOffsetY 0 alignOffsetZ 0
joint "Assemble3" OffsetX 0 OffsetY 0 OffsetZ 0 AngleZ 0 OffsetX 0 OffsetY 0 OffsetZ 0 AngleZ 0 alignAngle 0 alignOffsetX 0 alignOffsetY 0 alignOffsetZ 0
joint "Assemble4" OffsetX 0 OffsetY 0 OffsetZ 0 AngleZ 0 OffsetX 0 OffsetY 0 OffsetZ 0 AngleZ 0 alignAngle 0 alignOffsetX 0 alignOffsetY 0 alignOffsetZ 0
component_insert "Component Insert6"
component_insert "Component Insert7"
component_insert "Component Insert8"
component_insert "Component Insert9"
component_insert "Component Insert10"
component_insert "Component Insert11"
joint "Assemble6" OffsetX 0 OffsetY 0 OffsetZ 0 AngleZ 0 OffsetX 0 OffsetY 0 OffsetZ 0 AngleZ 0 alignAngle 180 alignOffsetX 0 alignOffsetY 0 alignOffsetZ 0
joint "Assemble7" OffsetX 0 OffsetY 0 OffsetZ 0 AngleZ 0 OffsetX 0 OffsetY 0 OffsetZ 0 AngleZ 0 alignAngle 180 alignOffsetX 0 alignOffsetY -22 alignOffsetZ 0 OffsetX 0 OffsetY 0 OffsetZ 0 AngleZ 0 OffsetX 0 OffsetY 0 OffsetZ 0 AngleZ 0
joint "Assemble8" OffsetX 0 OffsetY 0 OffsetZ 0 AngleZ 0 OffsetX 0 OffsetY 0 OffsetZ 0 AngleZ 0 alignAngle -90 alignOffsetX 0 alignOffsetY 0 alignOffsetZ 0
joint "Assemble9" OffsetX 0 OffsetY 0 OffsetZ 0 AngleZ 0 OffsetX 0 OffsetY 0 OffsetZ 0 AngleZ 0 alignAngle 0 alignOffsetX -22 alignOffsetY 0 alignOffsetZ 0 OffsetX 0 OffsetY 0 OffsetZ 0 AngleZ 0 OffsetX 0 OffsetY 0 OffsetZ 0 AngleZ 0
joint "Assemble10" OffsetX 0 OffsetY 0 OffsetZ 0 AngleZ 0 OffsetX 0 OffsetY 0 OffsetZ 0 AngleZ 0 alignAngle 180 alignOffsetX 11 alignOffsetY 0 alignOffsetZ 0 OffsetX 0 OffsetY 0 OffsetZ 0 AngleZ 0 OffsetX 0 OffsetY 0 OffsetZ 0 AngleZ 0
joint "Assemble11" OffsetX 0 OffsetY 0 OffsetZ 0 AngleZ 0 OffsetX 0 OffsetY 0 OffsetZ 0 AngleZ 0 alignAngle 180 alignOffsetX -11 alignOffsetY 0 alignOffsetZ 0 OffsetX 0 OffsetY 0 OffsetZ 0 AngleZ 0 OffsetX 0 OffsetY 0 OffsetZ 0 AngleZ 0
component_insert "Component Insert12"
component_insert "Component Insert13"
component_insert "Component Insert14"
joint "Assemble12" OffsetX 0 OffsetY 0 OffsetZ 0 AngleZ 0 OffsetX 0 OffsetY 0 OffsetZ 0 AngleZ 0 alignAngle 0 alignOffsetX 0 alignOffsetY 0 alignOffsetZ 0
joint "Assemble13" OffsetX 0 OffsetY 0 OffsetZ 0 AngleZ 0 OffsetX 0 OffsetY 0 OffsetZ 0 AngleZ 0 alignAngle 0 alignOffsetX 0 alignOffsetY 0 alignOffsetZ 0
joint "Assemble14" OffsetX 0 OffsetY 0 OffsetZ 0 AngleZ 0 OffsetX 0 OffsetY 0 OffsetZ 0 AngleZ 0 alignAngle 180 alignOffsetX 0 alignOffsetY -22 alignOffsetZ 0

design "EdgeBeacons_Base"
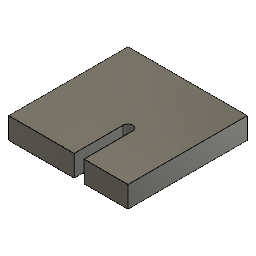
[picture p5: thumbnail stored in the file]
sketch "Sketch1" plane through (0, 0, 0) normal (0, 1, 0) x axis (1, 0, 0)
  line L1 (61, 61) -> (-61, 61)
  line L2 (61, -61) -> (61, 61)
  line L3 (-61, 61) -> (-61, -61)
  line L4 (61, -61) -> (-61, 61)
  line L5 (16, -11) -> (16, -61)
  line L6 (6, -61) -> (6, -11)
  line L7 (11, -11) -> (11, -61)
  line L8 (16, -61) -> (61, -61)
  line L9 (-61, -61) -> (6, -61)
  arc A1 centre (11, -11) radius 5 clockwise from (6, -11) to (16, -11)
  point P2 (-61, 61)
  point P3 (61, 61)
  point P10 (11, -61)
  point P11 (11, -11)
  dimension "d1" distance P2 P3 = 122
  dimension "d4" distance P10 P11 = 50
  dimension "d5" diameter A1 = 10
  dimension "d6" distance L2 L7 = 50
extrude "Extrude1" new body sketch "Sketch1" profile of L1 L2 L9 L3 along normal blind 22

design "EdgeBeacons_LargeBorder"
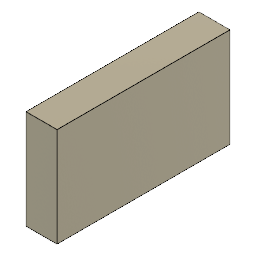
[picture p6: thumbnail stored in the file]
sketch "Sketch1" plane through (0, 0, 0) normal (1, 0, 0) x axis (0, 0, -1)
  line L1 (122, 70) -> (0, 70)
  line L2 (122, 0) -> (122, 70)
  line L3 (0, 0) -> (122, 0)
  line L4 (0, 70) -> (0, 0)
  point P1 (0, 0)
  point P5 (0, 0)
  point P2 (0, 70)
  point P3 (122, 70)
  horizontal L1
  vertical L2
  horizontal L3
  vertical L4
  coincident P1 P5
  dimension "d1" distance P2 P5 = 70 (= "48 mm + 22 mm")
  dimension "d2" distance P2 P3 = 122
extrude "Extrude1" new body sketch "Sketch1" along normal blind 22

design "TaquetCentre"
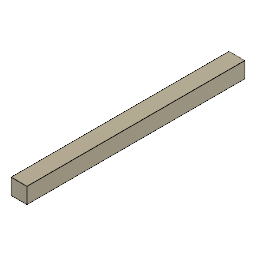
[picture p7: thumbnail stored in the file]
sketch "Sketch1" plane through (0, 0, 0) normal (0, 1, 0) x axis (1, 0, 0)
  line L1 (11, 0) -> (-11, 0)
  line L2 (11, 300) -> (11, 0)
  line L3 (11, 0) -> (-11, 300)
  line L4 (-11, 0) -> (-11, 300)
  point P1 (0, 0)
  horizontal L1
  vertical L2
  horizontal L3
  vertical L4
  dimension "d1" = 300
  dimension "d2" distance P1 L2 = 11
  dimension "d3" distance L2 L4 = 22
extrude "Extrude1" new body sketch "Sketch1" along normal blind 22

design "Table2020" references "TaquetCentre", "PaintExperience", "manchonJaune", "manchonBleu", "taquet", "ROUE_MINI_V3_ASSEMBLAGE", "BaseTable", "Rocher", "ZoneRocheuse"
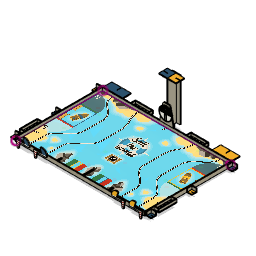
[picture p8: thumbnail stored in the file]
component_insert "Component Insert1" OffsetX 0 OffsetY 0 OffsetZ 0 AngleZ 0 OffsetX 0 OffsetY 0 OffsetZ 0 AngleZ 0 OffsetX 0 OffsetY 0 OffsetZ 0 AngleZ 0 OffsetX 0 OffsetY 0 OffsetZ 0 AngleZ 0 OffsetX 0 OffsetY 0 OffsetZ 0 AngleZ 0 OffsetX 0 OffsetY 0 OffsetZ 0 AngleZ 0 OffsetX 0 OffsetY 0 OffsetZ 0 AngleZ 0 OffsetX 0 OffsetY 0 OffsetZ 0 AngleZ 0
ground "Ground1"
sketch "Sketch1" plane through (0, 22, 0) normal (0, 1, 0) x axis (-1, 0, 0)
  line L1 (-3000, 2000) -> (0, 2000)
  line L2 (-3000, 0) -> (-3000, 2000)
  line L3 (0, 0) -> (-3000, 0)
  line L4 (0, 2000) -> (0, 0)
component_insert "Component Insert7"
component_insert "Component Insert23"
position "Position9"
component_insert "Component Insert24"
position "Position10"
component_insert "Component Insert25"
component_insert "Component Insert26"
position "Position11"
component_insert "Component Insert27"
position "Position12"
joint "Assemble17" OffsetX 0 OffsetY 0 OffsetZ 0 AngleZ 0 OffsetX 0 OffsetY 0 OffsetZ 0 AngleZ 0 alignAngle 0 alignOffsetX 0 alignOffsetY 0 alignOffsetZ 0
joint "Assemble18" OffsetX 0 OffsetY 0 OffsetZ 0 AngleZ 0 OffsetX 0 OffsetY 0 OffsetZ 0 AngleZ 0 alignAngle 0 alignOffsetX 0 alignOffsetY 0 alignOffsetZ 0
position "Position13"
component_insert "Component Insert29"
joint "Assemble24" OffsetX 0 OffsetY 0 OffsetZ 0 AngleZ 0 OffsetX 0 OffsetY 0 OffsetZ 0 AngleZ 0 alignAngle 90 alignOffsetX -2770 alignOffsetY -25 alignOffsetZ 0
component_insert "Component Insert30"
joint "Assemble25" OffsetX 0 OffsetY 0 OffsetZ 0 AngleZ 0 OffsetX 0 OffsetY 0 OffsetZ 0 AngleZ 0 alignAngle 0 alignOffsetX -25 alignOffsetY -2360 alignOffsetZ 0 OffsetX 0 OffsetY 0 OffsetZ 0 AngleZ 0 OffsetX 0 OffsetY 0 OffsetZ 0 AngleZ 0
component_insert "Component Insert33"
joint "Assemble28" OffsetX 0 OffsetY 0 OffsetZ 0 AngleZ 0 alignAngle 0 alignOffsetX 0 alignOffsetY 0 alignOffsetZ 900 OffsetX 0 OffsetY 0 OffsetZ 0 AngleZ 0 OffsetX 0 OffsetY 0 OffsetZ 0 AngleZ 0
component_insert "Component Insert34"
joint "Assemble29" OffsetX 0 OffsetY 0 OffsetZ 0 AngleZ 0 OffsetX 0 OffsetY 0 OffsetZ 0 AngleZ 0 alignAngle 0 alignOffsetX 0 alignOffsetY 0 alignOffsetZ 2100 OffsetX 0 OffsetY 0 OffsetZ 0 AngleZ 0 OffsetX 0 OffsetY 0 OffsetZ 0 AngleZ 0
joint "Assemble30" OffsetX 0 OffsetY 0 OffsetZ 0 AngleZ 0 OffsetX 0 OffsetY 0 OffsetZ 0 AngleZ 0 alignAngle 0 alignOffsetX -22 alignOffsetY 15 alignOffsetZ -850 OffsetX 0 OffsetY 0 OffsetZ 0 AngleZ 0 OffsetX 0 OffsetY 0 OffsetZ 0 AngleZ 0 OffsetX 0 OffsetY 0 OffsetZ 0 AngleZ 0 OffsetX 0 OffsetY 0 OffsetZ 0 AngleZ 0 OffsetX 0 OffsetY 0 OffsetZ 0 AngleZ 0 OffsetX 0 OffsetY 0 OffsetZ 0 AngleZ 0
joint "Assemble31" OffsetX 0 OffsetY 0 OffsetZ 0 AngleZ 0 OffsetX 0 OffsetY 0 OffsetZ 0 AngleZ 0 alignAngle 0 alignOffsetX -22 alignOffsetY 15 alignOffsetZ -2150 (= "-3000 mm + 850 mm") OffsetX 0 OffsetY 0 OffsetZ 0 AngleZ 0 OffsetX 0 OffsetY 0 OffsetZ 0 AngleZ 0 OffsetX 0 OffsetY 0 OffsetZ 0 AngleZ 0 OffsetX 0 OffsetY 0 OffsetZ 0 AngleZ 0 OffsetX 0 OffsetY 0 OffsetZ 0 AngleZ 0 OffsetX 0 OffsetY 0 OffsetZ 0 AngleZ 0 OffsetX 0 OffsetY 0 OffsetZ 0 AngleZ 0 OffsetX 0 OffsetY 0 OffsetZ 0 AngleZ 0
joint "Assemble32" OffsetX 0 OffsetY 0 OffsetZ 0 AngleZ 0 alignAngle 0 alignOffsetX -22 alignOffsetY 15 alignOffsetZ 1600 OffsetX 0 OffsetY 0 OffsetZ 0 AngleZ 0 OffsetX 0 OffsetY 0 OffsetZ 0 AngleZ 0 OffsetX 0 OffsetY 0 OffsetZ 0 AngleZ 0
joint "Assemble33" OffsetX 0 OffsetY 0 OffsetZ 0 AngleZ 0 alignAngle 180 alignOffsetX 22 alignOffsetY -15 alignOffsetZ -1600 OffsetX 0 OffsetY 0 OffsetZ 0 AngleZ 0 OffsetX 0 OffsetY 0 OffsetZ 0 AngleZ 0 OffsetX 0 OffsetY 0 OffsetZ 0 AngleZ 0
component_insert "Component Insert38"
joint "Assemble38" OffsetX 0 OffsetY 0 OffsetZ 0 AngleZ 0 OffsetX 0 OffsetY 0 OffsetZ 0 AngleZ 0 alignAngle 0 alignOffsetX 0 alignOffsetY 0 alignOffsetZ 0 OffsetX 0 OffsetY 0 OffsetZ 0 AngleZ 0 OffsetX 0 OffsetY 0 OffsetZ 0 AngleZ 0
component_insert "Component Insert37"
position "Position14"
joint "Assemble35" OffsetX 0 OffsetY 0 OffsetZ 0 AngleZ 0 OffsetX 0 OffsetY 0 OffsetZ 0 AngleZ 0 alignAngle 0 alignOffsetX 0 alignOffsetY 70 alignOffsetZ 0 OffsetX 0 OffsetY 0 OffsetZ 0 AngleZ 0 OffsetX 0 OffsetY 0 OffsetZ 0 AngleZ 0 OffsetX 0 OffsetY 0 OffsetZ 0 AngleZ 0 OffsetX 0 OffsetY 0 OffsetZ 0 AngleZ 0
sketch "Sketch3" plane through (0, 92, 0) normal (0, 1, 0) x axis (-1, 0, 0)
  line L1 (-3000, 2022) -> (0, 2022)
  line L2 (-3000, 2000) -> (-3000, 2022)
  line L3 (0, 2000) -> (-3000, 2000)
  line L4 (0, 2022) -> (0, 2000)
  line L5 (-1050, 2022) -> (-1050, 2000)
  line L6 (-1150, 2022) -> (-1150, 2000)
  line L7 (-1250, 2022) -> (-1250, 2000)
  line L8 (-1350, 2022) -> (-1350, 2000)
  line L9 (-1650, 2022) -> (-1650, 2000)
  line L10 (-1750, 2022) -> (-1750, 2000)
  line L11 (-1850, 2022) -> (-1850, 2000)
  line L12 (-1950, 2022) -> (-1950, 2000)
  line L13 (-2365, 2022) -> (-2365, 2000)
  line L14 (-2770, 2022) -> (-2770, 2000)
  line L15 (-230, 2022) -> (-230, 2000)
  line L16 (-635, 2022) -> (-635, 2000)
  line L17 (-400, 2022) -> (-400, 2000)
  point P6 (-1050, 2000)
  point P7 (-1050, 2022)
  point P8 (-1150, 2000)
  point P9 (-1150, 2022)
  point P10 (-1250, 2000)
  point P11 (-1250, 2022)
  point P12 (-1350, 2000)
  point P13 (-1350, 2022)
  point P14 (-1650, 2000)
  point P15 (-1650, 2022)
  point P16 (-1750, 2000)
  point P17 (-1750, 2022)
  point P18 (-1850, 2000)
  point P19 (-1850, 2022)
  point P20 (-1950, 2000)
  point P21 (-1950, 2022)
  point P22 (-2365, 2000)
  point P23 (-2365, 2022)
  point P24 (-2770, 2000)
  point P25 (-2770, 2022)
  point P26 (-230, 2000)
  point P27 (-230, 2022)
  point P28 (-635, 2000)
  point P29 (-635, 2022)
  point P30 (-400, 2000)
  point P31 (-400, 2022)
  coincident L3 P6
  coincident L1 P7
  perpendicular L1 L5
  coincident L3 P8
  coincident L1 P9
  perpendicular L1 L6
  coincident L3 P10
  coincident L1 P11
  perpendicular L1 L7
  coincident L3 P12
  coincident L1 P13
  perpendicular L1 L8
  coincident L3 P14
  coincident L1 P15
  perpendicular L1 L9
  coincident L3 P16
  coincident L1 P17
  perpendicular L1 L10
  coincident L3 P18
  coincident L1 P19
  perpendicular L1 L11
  coincident L3 P20
  coincident L1 P21
  perpendicular L1 L12
  coincident L3 P22
  coincident L1 P23
  perpendicular L1 L13
  coincident L3 P24
  coincident L1 P25
  perpendicular L1 L14
  coincident L3 P26
  coincident L1 P27
  perpendicular L1 L15
  coincident L3 P28
  coincident L1 P29
  perpendicular L1 L16
  coincident L3 P30
  coincident L1 P31
  perpendicular L1 L17
  dimension "d685" distance L4 L5 = 1050
  dimension "d686" distance L4 L6 = 1150
  dimension "d687" distance L4 L7 = 1250
  dimension "d688" distance L4 L8 = 1350
  dimension "d689" distance L2 L12 = 1050
  dimension "d690" distance L2 L11 = 1150
  dimension "d691" distance L2 L10 = 1250
  dimension "d692" distance L2 L9 = 1350
  dimension "d693" distance L2 L14 = 230
  dimension "d694" distance L2 L13 = 635
  dimension "d695" distance L4 L15 = 230
  dimension "d696" distance L4 L16 = 635
  dimension "d705" distance L4 L17 = 400
sketch "Sketch4" plane through (0, 92, 0) normal (0, 1, 0) x axis (-1, 0, 0)
  line L1 (22, 2022) -> (22, -22)
  line L2 (0, 2022) -> (22, 2022)
  line L3 (0, -22) -> (0, 2022)
  line L4 (22, -22) -> (0, -22)
  line L5 (22, 1700) -> (0, 1700)
  line L6 (22, 1600) -> (0, 1600)
  line L7 (22, 1500) -> (0, 1500)
  line L8 (22, 1100) -> (0, 1100)
  line L9 (22, 1070) -> (0, 1070)
  line L10 (22, 530) -> (0, 530)
  line L11 (22, 500) -> (0, 500)
  line L12 (22, 100) -> (0, 100)
  line L13 (0, 0) -> (-3000, 0)
  point P6 (0, 1700)
  point P7 (22, 1700)
  point P8 (0, 1600)
  point P9 (22, 1600)
  point P10 (0, 1500)
  point P11 (22, 1500)
  point P12 (0, 1100)
  point P13 (22, 1100)
  point P14 (0, 1070)
  point P15 (22, 1070)
  point P16 (0, 530)
  point P17 (22, 530)
  point P18 (0, 500)
  point P19 (22, 500)
  point P20 (0, 100)
  point P21 (22, 100)
  coincident L3 P6
  coincident L1 P7
  perpendicular L1 L5
  coincident L3 P8
  coincident L1 P9
  perpendicular L1 L6
  coincident L3 P10
  coincident L1 P11
  perpendicular L1 L7
  coincident L3 P12
  coincident L1 P13
  perpendicular L1 L8
  coincident L3 P14
  coincident L1 P15
  perpendicular L1 L9
  coincident L3 P16
  coincident L1 P17
  perpendicular L1 L10
  coincident L3 P18
  coincident L1 P19
  perpendicular L1 L11
  coincident L3 P20
  coincident L1 P21
  perpendicular L1 L12
  dimension "d697" distance L7 L13 = 1500
  dimension "d698" distance L8 L13 = 1100
  dimension "d699" distance L9 L13 = 1070
  dimension "d700" distance L10 L13 = 530
  dimension "d701" distance L11 L13 = 500
  dimension "d702" distance L12 L13 = 100
  dimension "d703" distance L6 L13 = 1600
  dimension "d704" distance L5 L13 = 1700
sketch "Sketch1" plane through (0, 92, 0) normal (0, 1, 0) x axis (-1, 0, 0)
  line L1 (134, 1390.5) -> (112, 1390.5)
  line L2 (134, 1809.5) -> (134, 1390.5)
  line L3 (112, 1809.5) -> (134, 1809.5)
  line L4 (112, 1390.5) -> (112, 1809.5)
  line L5 (0, 1809.5) -> (134, 1809.5)
  line L6 (0, 1390.5) -> (0, 1809.5)
  line L7 (134, 1390.5) -> (0, 1390.5)
  line L8 (134, 1809.5) -> (134, 1390.5)
  line L9 (22, 1412.5) -> (22, 1787.5)
  line L10 (112, 1412.5) -> (22, 1412.5)
  line L11 (112, 1787.5) -> (112, 1412.5)
  line L12 (22, 1787.5) -> (112, 1787.5)
  circle C1 centre (67, 1450) radius 28
  circle C2 centre (67, 1525) radius 28
  circle C3 centre (67, 1600) radius 28
  circle C4 centre (67, 1675) radius 28
  circle C5 centre (67, 1750) radius 28
  point P4 (134, 1809.5)
  point P6 (134, 1809.5)
  horizontal L5
  vertical L6
  horizontal L7
  vertical L8
  coincident P4 P6
  dimension "d726" distance L5 L7 = 419
extrude "Extrude1" new body sketch "Sketch1" profile of L1 L2 L3 L4 L5 L6 L7 L8 L9 L10 L11 L12 along normal blind 0.3
sketch "Sketch1" plane through (0, 92, 0) normal (0, 1, 0) x axis (-1, 0, 0)
  line L1 (-3134, 1809.5) -> (-3112, 1809.5)
  line L2 (-3134, 1390.5) -> (-3134, 1809.5)
  line L3 (-3112, 1390.5) -> (-3134, 1390.5)
  line L4 (-3112, 1809.5) -> (-3112, 1390.5)
  line L5 (-3000, 1390.5) -> (-3134, 1390.5)
  line L6 (-3000, 1809.5) -> (-3000, 1390.5)
  line L7 (-3134, 1809.5) -> (-3000, 1809.5)
  line L8 (-3134, 1390.5) -> (-3134, 1809.5)
  line L9 (-3022, 1787.5) -> (-3022, 1412.5)
  line L10 (-3112, 1787.5) -> (-3022, 1787.5)
  line L11 (-3112, 1412.5) -> (-3112, 1787.5)
  line L12 (-3022, 1412.5) -> (-3112, 1412.5)
  circle C1 centre (-3067, 1750) radius 28
  circle C2 centre (-3067, 1675) radius 28
  circle C3 centre (-3067, 1600) radius 28
  circle C4 centre (-3067, 1525) radius 28
  circle C5 centre (-3067, 1450) radius 28
  point P4 (-3134, 1390.5)
  point P6 (-3134, 1390.5)
  horizontal L5
  vertical L6
  horizontal L7
  vertical L8
  coincident P4 P6
  dimension "d729" distance L5 L7 = 419
extrude "Extrude1" new body sketch "Sketch1" profile of L1 L2 L3 L4 L5 L6 L7 L8 L9 L10 L11 L12 along normal blind 0.3
sketch "Sketch1" plane through (0, 22, 0) normal (0, 1, 0) x axis (-1, 0, 0)
  line L1 (-3000, 2000) -> (0, 2000)
  line L2 (-3000, 0) -> (-3000, 2000)
  line L3 (0, 0) -> (-3000, 0)
  line L4 (0, 2000) -> (0, 0)
  line L5 (-1550, 1200) -> (-1450, 1200)
  line L6 (-1550, 1300) -> (-1550, 1200)
  line L7 (-1450, 1300) -> (-1550, 1300)
  line L8 (-1450, 1200) -> (-1450, 1300)
  line L9 (0, 2022) -> (0, -22)
  line L10 (0, 0) -> (-3000, 0)
  point P6 (-1450, 1200)
  point P7 (-1550, 1200)
  point P9 (-1450, 1300)
  horizontal L5
  vertical L6
  horizontal L7
  vertical L8
  dimension "d732" distance L8 L9 = 1450
  dimension "d733" distance L5 L10 = 1200
  dimension "d734" distance P6 P7 = 100
  dimension "d735" distance P6 P9 = 100
component_insert "Component Insert39"
joint "Assemble39" OffsetX 0 OffsetY 0 OffsetZ 0 AngleZ 0 OffsetX 0 OffsetY 0 OffsetZ 0 AngleZ 0 alignAngle 0 alignOffsetX -25 alignOffsetY -230 alignOffsetZ 0
component_insert "Component Insert40"
joint "Assemble40" OffsetX 0 OffsetY 0 OffsetZ 0 AngleZ 0 OffsetX 0 OffsetY 0 OffsetZ 0 AngleZ 0 alignAngle 0 alignOffsetX -25 alignOffsetY -635 alignOffsetZ 0
component_insert "Component Insert41"
joint "Assemble41" OffsetX 0 OffsetY 0 OffsetZ 0 AngleZ 0 OffsetX 0 OffsetY 0 OffsetZ 0 AngleZ 0 alignAngle 0 alignOffsetX 0 alignOffsetY 0 alignOffsetZ 0 OffsetX 0 OffsetY 0 OffsetZ 0 AngleZ 0 OffsetX 0 OffsetY 0 OffsetZ 0 AngleZ 0
component_insert "Component Insert42"
joint "Assemble43" OffsetX 0 OffsetY 0 OffsetZ 0 AngleZ 0 OffsetX 0 OffsetY 0 OffsetZ 0 AngleZ 0 alignAngle -90 alignOffsetX 0 alignOffsetY 0 alignOffsetZ 0
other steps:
joint_origin "JointOrigin8" OffsetX 0 OffsetY 0 OffsetZ 0 AngleZ 0
joint_origin "JointOrigin13" OffsetX 0 OffsetY 0 OffsetZ 0 AngleZ 0
joint_origin "JointOrigin14" OffsetX 0 OffsetY 0 OffsetZ 0 AngleZ 0
create_component "CreateComponent1"
create_component "CreateComponent2"
create_component "CreateComponent3"

design "Balise Verte"
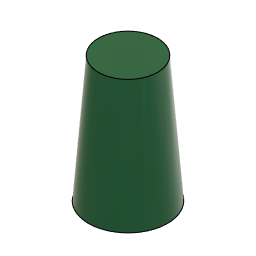
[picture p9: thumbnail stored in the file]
sketch "Sketch1" plane through (0, 0, 0) normal (1, 0, 0) x axis (0, 0, -1)
  line L1 (-36, 0) -> (0, 0)
  line L2 (-27, 115) -> (-36, 0)
  line L3 (0, 115) -> (-27, 115)
  line L4 (0, 0) -> (0, 115)
  line L5 (-25.6128, 113.5) -> (0, 113.5)
  line L6 (-34.4954, 0) -> (-25.6128, 113.5)
  line L7 (0, 0) -> (-34.4954, 0)
  point P1 (0, 0)
  point P2 (0, 0)
  point P6 (0, 0)
  point P7 (0, 113.5)
  point P10 (0, 0)
  point P4 (-27, 115)
  point P5 (0, 115)
  point P3 (-36, 0)
  coincident P1 P2
  horizontal L1
  parallel L1 L3
  coincident P1 P6
  perpendicular L1 L4
  coincident L4 P7
  perpendicular L4 L5
  coincident L4 P10
  perpendicular L4 L7
  collinear L1 L7
  parallel L2 L6
  dimension "d1" distance P4 P5 = 27 (= "( 54 / 2 ) * 1 mm")
  dimension "d2" distance L1 L3 = 115
  dimension "d3" distance P2 P3 = 36 (= "( 72 / 2 ) * 1 mm")
  dimension "d5" distance L3 L5 = 1.5
  dimension "d6" distance L2 L6 = 1.5
revolve "Revolve1" sketch "Sketch1" AlongAngle 360

design "Edge Beacon Left" references "EdgeBeacons_SmallBorder", "EdgeBeacons_LargeBorder", "EdgeBeacons_Base"
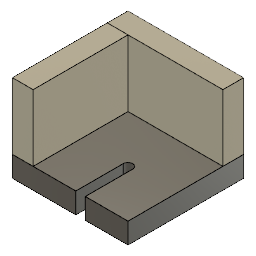
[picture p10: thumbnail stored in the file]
component_insert "Component Insert1"
ground "Ground1"
component_insert "Component Insert2"
component_insert "Component Insert3"
joint "Assemble1" OffsetX 0 OffsetY 0 OffsetZ 0 AngleZ 0 OffsetX 0 OffsetY 0 OffsetZ 0 AngleZ 0 alignAngle 0 alignOffsetX 0 alignOffsetY 0 alignOffsetZ 0
joint "Assemble2" OffsetX 0 OffsetY 0 OffsetZ 0 AngleZ 0 OffsetX 0 OffsetY 0 OffsetZ 0 AngleZ 0 alignAngle 0 alignOffsetX 0 alignOffsetY 0 alignOffsetZ 0

design "Ground"
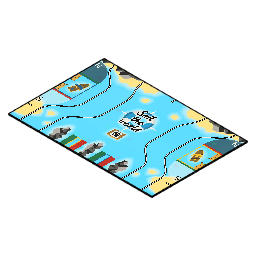
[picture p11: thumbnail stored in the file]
sketch "Sketch1" plane through (0, 0, 0) normal (0, 1, 0) x axis (1, 0, 0)
  line L1 (3000, 0) -> (0, 0)
  line L2 (3000, -2000) -> (3000, 0)
  line L3 (0, -2000) -> (3000, -2000)
  line L4 (0, 0) -> (0, -2000)
  point P1 (0, 0)
  point P2 (0, 0)
  point P5 (0, -2000)
  point P3 (3000, 0)
  horizontal L1
  vertical L2
  horizontal L3
  vertical L4
  coincident P1 P2
  dimension "d1" distance P2 P5 = 2000
  dimension "d2" distance P1 P3 = 3000
  dimension "d5" AlongDistance = 0.1
  dimension "d6" TaperAngle = 0
  dimension "d7" distance = 300
  dimension "d8" distance = 450
  dimension "d12" uSpaceDistance = -300
  dimension "d13" vSpaceDistance = 0
  dimension "d15" distance = 1050
  dimension "d16" distance = 1000
  dimension "d17" diameter = 300
  dimension "d18" AlongDistance = 0.5
  dimension "d19" TaperAngle = 0
  dimension "d21" diameter = 2
  dimension "d22" AlongDistance = 0.1
  dimension "d23" TaperAngle = 0
  dimension "d24" distance = 300
  dimension "d25" distance = 50
  dimension "d30" AlongDistance = 0.2
  dimension "d31" TaperAngle = 0
  dimension "d32" diameter = 299.8
extrude "Extrude1" new body sketch "Sketch1" along normal blind 22
decal "Decal2"
decal "Decal3"
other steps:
decal "Decal1"

design "ROUE_V3"
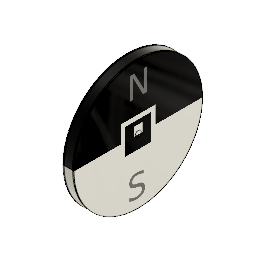
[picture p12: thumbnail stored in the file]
